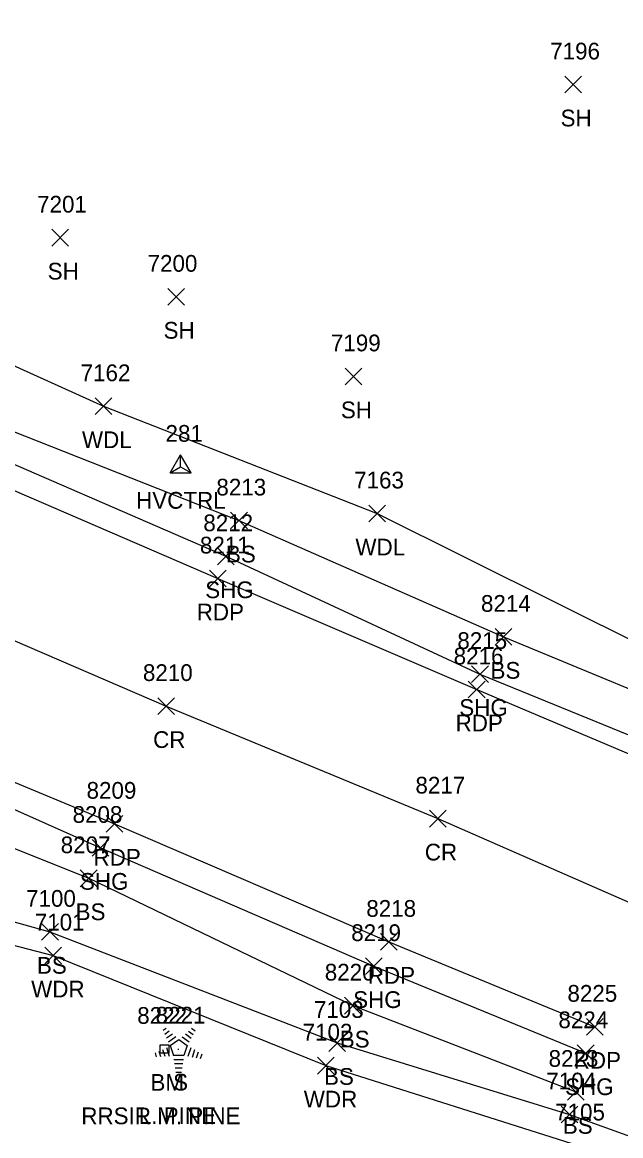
# Model space of a CAD drawing. Extents: x 1588028 to 1589597, y 137576 to 138176.
# Drawn here: x 1589378.5 to 1589450, y 137659.5 to 137792.6 of the extents above; entities that cross this region are included whole.
import ezdxf

# ---------------------------------------------------------------- set-up
doc = ezdxf.new("R2010")
doc.units = 0
for name, color, linetype in [('C_A', 7, 'Continuous'), ('C_C', 7, 'Continuous'), ('C_I', 7, 'Continuous'), ('CPBM', 7, 'Continuous'), ('CPSM', 7, 'Continuous'), ('L_A', 7, 'Continuous'), ('L_C', 7, 'Continuous'), ('L_I', 7, 'Continuous'), ('L_TIC', 7, 'Continuous'), ('LAWA', 7, 'Continuous'), ('LELB', 7, 'Continuous'), ('LTC', 7, 'Continuous'), ('P_A', 7, 'Continuous'), ('P_I', 7, 'Continuous'), ('P_TIC', 7, 'Continuous'), ('PET', 7, 'Continuous'), ('PRC', 7, 'Continuous'), ('PSU', 7, 'Continuous')]:
    doc.layers.add(name, color=color, linetype=linetype)

msp = doc.modelspace()

# ---------------------------------------------------------------- linework, layer by layer
at = {"layer": 'CPBM'}
for p, q in [((1589395.01, 137669.4), (1589395.01, 137670.4)), ((1589395.01, 137670.4), (1589396.01, 137670.4)), ((1589396.01, 137669.4), (1589395.01, 137669.4)), ((1589395.51, 137669.9), (1589395.51, 137669.9)), ((1589395.51, 137669.9), (1589395.51, 137669.9)), ((1589396.01, 137670.4), (1589396.01, 137669.4))]:
    msp.add_line(p, q, dxfattribs=at)
at = {"layer": 'CPSM'}
for p, q in [((1589396.18, 137738.74), (1589397.43, 137740.9)), ((1589398.68, 137738.74), (1589397.43, 137740.9)), ((1589397.43, 137739.46), (1589397.43, 137740.9)), ((1589396.18, 137738.74), (1589397.43, 137739.46)), ((1589396.18, 137738.74), (1589398.68, 137738.74)), ((1589397.43, 137739.46), (1589397.43, 137739.46)), ((1589397.43, 137739.46), (1589398.68, 137738.74))]:
    msp.add_line(p, q, dxfattribs=at)
at = {"layer": 'L_TIC'}
for points in [[(1589443.34, 137784.15), (1589445.34, 137786.15)], [(1589445.34, 137784.15), (1589443.34, 137786.15)], [(1589382.06, 137765.85), (1589384.06, 137767.85)], [(1589384.06, 137765.85), (1589382.06, 137767.85)], [(1589395.91, 137758.78), (1589397.91, 137760.78)], [(1589397.91, 137758.78), (1589395.91, 137760.78)], [(1589417.09, 137749.27), (1589419.09, 137751.27)], [(1589419.09, 137749.27), (1589417.09, 137751.27)], [(1589387.23, 137745.7), (1589389.23, 137747.7)], [(1589389.23, 137745.7), (1589387.23, 137747.7)], [(1589419.91, 137732.88), (1589421.91, 137734.88)], [(1589421.91, 137732.88), (1589419.91, 137734.88)], [(1589403.41, 137732.04), (1589405.41, 137734.04)], [(1589405.41, 137732.04), (1589403.41, 137734.04)], [(1589435.02, 137718.14), (1589437.02, 137720.14)], [(1589437.02, 137718.14), (1589435.02, 137720.14)], [(1589385.45, 137689.29), (1589387.45, 137691.29)], [(1589387.45, 137689.29), (1589385.45, 137691.29)], [(1589380.83, 137682.89), (1589382.83, 137684.89)], [(1589382.83, 137682.89), (1589380.83, 137684.89)], [(1589381.22, 137680.05), (1589383.22, 137682.05)], [(1589383.22, 137680.05), (1589381.22, 137682.05)], [(1589417.01, 137674.07), (1589419.01, 137676.07)], [(1589419.01, 137674.07), (1589417.01, 137676.07)], [(1589415.13, 137669.61), (1589417.13, 137671.61)], [(1589417.13, 137669.61), (1589415.13, 137671.61)], [(1589413.78, 137666.9), (1589415.78, 137668.9)], [(1589415.78, 137666.9), (1589413.78, 137668.9)], [(1589443.66, 137663.76), (1589445.66, 137665.76)], [(1589445.66, 137663.76), (1589443.66, 137665.76)], [(1589442.9, 137661.06), (1589444.9, 137663.06)], [(1589444.9, 137661.06), (1589442.9, 137663.06)]]:
    msp.add_lwpolyline(points, dxfattribs=at)
at = {"layer": 'LAWA'}
for points in [[(1589191.48, 137827.66), (1589208.47, 137821.19), (1589231.01, 137810.22), (1589260.79, 137799.99), (1589288.54, 137790.36), (1589312.49, 137778.55), (1589337.68, 137767.31), (1589356.85, 137760.89), (1589388.23, 137746.7), (1589420.91, 137733.88), (1589453.12, 137717.84), (1589474.94, 137709.38)], [(1589349.24, 137689.61), (1589382.22, 137681.05), (1589414.78, 137667.9), (1589444.95, 137658.35), (1589471.13, 137649.8)]]:
    msp.add_lwpolyline(points, dxfattribs=at)
at = {"layer": 'LELB'}
for points in [[(1589357.82, 137751.59), (1589375.51, 137744.43), (1589404.41, 137733.04), (1589436.02, 137719.14), (1589462.97, 137707.98)], [(1589348.76, 137705.36), (1589386.45, 137690.29), (1589418.01, 137675.07), (1589444.66, 137664.76)], [(1589349.04, 137693.04), (1589381.83, 137683.89), (1589416.13, 137670.61), (1589443.9, 137662.06), (1589473.48, 137651.39)]]:
    msp.add_lwpolyline(points, dxfattribs=at)
at = {"layer": 'LTC'}
for p, q in [((1589395.34, 137672.14), (1589395.7, 137672.4)), ((1589395.55, 137671.68), (1589396.08, 137672.06)), ((1589398.37, 137672.03), (1589398.92, 137671.64)), ((1589398.74, 137672.38), (1589399.16, 137672.08)), ((1589395.76, 137671.21), (1589396.47, 137671.72)), ((1589395.97, 137670.75), (1589396.85, 137671.38)), ((1589396.2, 137670.29), (1589397.21, 137671.02)), ((1589397.21, 137671.02), (1589398.21, 137670.3)), ((1589397.63, 137671.34), (1589398.44, 137670.75)), ((1589398, 137671.69), (1589398.68, 137671.19)), ((1589394.38, 137669.42), (1589394.53, 137668.95)), ((1589394.83, 137669.64), (1589395.04, 137668.99)), ((1589395.29, 137669.85), (1589395.56, 137669.02)), ((1589395.74, 137670.07), (1589396.07, 137669.05)), ((1589396.2, 137670.29), (1589396.59, 137669.1)), ((1589398.21, 137670.3), (1589397.82, 137669.1)), ((1589398.64, 137670.03), (1589398.31, 137668.99)), ((1589399.09, 137669.78), (1589398.8, 137668.89)), ((1589399.53, 137669.53), (1589399.3, 137668.8)), ((1589397.82, 137669.1), (1589396.59, 137669.1)), ((1589397.78, 137668.6), (1589396.63, 137668.6)), ((1589397.69, 137668.1), (1589396.71, 137668.1)), ((1589399.98, 137669.28), (1589399.79, 137668.7)), ((1589397.61, 137667.6), (1589396.78, 137667.6)), ((1589397.53, 137667.1), (1589396.85, 137667.1))]:
    msp.add_line(p, q, dxfattribs=at)
at = {"layer": 'P_TIC'}
for points in [[(1589401.84, 137727.77), (1589403.84, 137729.77)], [(1589403.84, 137727.77), (1589401.84, 137729.77)], [(1589400.87, 137725.11), (1589402.87, 137727.11)], [(1589402.87, 137725.11), (1589400.87, 137727.11)], [(1589432.2, 137713.7), (1589434.2, 137715.7)], [(1589434.2, 137713.7), (1589432.2, 137715.7)], [(1589431.81, 137711.85), (1589433.81, 137713.85)], [(1589433.81, 137711.85), (1589431.81, 137713.85)], [(1589394.71, 137709.87), (1589396.71, 137711.87)], [(1589396.71, 137709.87), (1589394.71, 137711.87)], [(1589388.55, 137695.8), (1589390.55, 137697.8)], [(1589390.55, 137695.8), (1589388.55, 137697.8)], [(1589427.18, 137696.42), (1589429.18, 137698.42)], [(1589429.18, 137696.42), (1589427.18, 137698.42)], [(1589386.87, 137692.92), (1589388.87, 137694.92)], [(1589388.87, 137692.92), (1589386.87, 137694.92)], [(1589421.31, 137681.69), (1589423.31, 137683.69)], [(1589423.31, 137681.69), (1589421.31, 137683.69)], [(1589419.52, 137678.79), (1589421.52, 137680.79)], [(1589421.52, 137678.79), (1589419.52, 137680.79)], [(1589445.91, 137671.54), (1589447.91, 137673.54)], [(1589447.91, 137671.54), (1589445.91, 137673.54)], [(1589444.83, 137668.38), (1589446.83, 137670.38)], [(1589446.83, 137668.38), (1589444.83, 137670.38)]]:
    msp.add_lwpolyline(points, dxfattribs=at)
at = {"layer": 'PET'}
for points in [[(1588976.42, 137837.98), (1588964.71, 137855.4), (1588953.74, 137871.46), (1588980.82, 137866.91), (1589021.21, 137859.55), (1589054.58, 137852.92), (1589087.36, 137843.77), (1589127.64, 137831.45), (1589150.05, 137824.37), (1589196.14, 137808.72), (1589243.87, 137790.96), (1589276.87, 137778.08), (1589322.25, 137759.62), (1589367.82, 137740.82), (1589401.87, 137726.11), (1589432.81, 137712.85), (1589459.76, 137701.46)], [(1588976.42, 137837.98), (1589015.38, 137829.77), (1589047.77, 137821.87), (1589087.62, 137811.07), (1589117.34, 137801.67), (1589165.82, 137785.25), (1589185.23, 137778.17), (1589232.28, 137760.8), (1589265.32, 137747.81), (1589310.31, 137729.83), (1589359.63, 137709.23), (1589389.55, 137696.8), (1589422.31, 137682.69), (1589446.91, 137672.54)]]:
    msp.add_lwpolyline(points, dxfattribs=at)
at = {"layer": 'PRC'}
msp.add_lwpolyline([(1588964.71, 137855.4), (1588980.14, 137852.51), (1589018.19, 137844.35), (1589051.57, 137836.27), (1589092.27, 137825.07), (1589122.68, 137816.23), (1589170.7, 137800.29), (1589190.72, 137793.38), (1589238.44, 137775.62), (1589271.31, 137762.4), (1589315.94, 137744.35), (1589366.22, 137723.58), (1589395.71, 137710.87), (1589428.18, 137697.42), (1589453.33, 137686.42)], dxfattribs=at)
at = {"layer": 'PSU'}
for points in [[(1589152.74, 137827.96), (1589197.07, 137811.88), (1589244.81, 137793.79), (1589277.33, 137781.11), (1589323.36, 137762.65), (1589353.23, 137749.52), (1589368.68, 137743.62), (1589402.84, 137728.77), (1589433.2, 137714.7), (1589460.72, 137703.44)], [(1589136.35, 137790.83), (1589164.04, 137781.22), (1589184.55, 137774.07), (1589230.78, 137756.58), (1589263.84, 137744.47), (1589309.17, 137726.92), (1589358.43, 137707.04), (1589387.87, 137693.92), (1589420.52, 137679.79), (1589445.83, 137669.38)]]:
    msp.add_lwpolyline(points, dxfattribs=at)

# ---------------------------------------------------------------- texts
at = {"layer": 'C_A'}
for s, p in [('HVCTRL', (1589392.12, 137734.46)), ('BM', (1589393.83, 137664.9))]:
    msp.add_text(s, height=2, dxfattribs=at).set_placement(p)
at = {"layer": 'C_C'}
msp.add_text('RRSIR M. PINE', height=2, dxfattribs=at).set_placement((1589385.57, 137660.9))
at = {"layer": 'C_I'}
for s, p in [('281', (1589395.63, 137742.46)), ('8222', (1589392.25, 137672.9))]:
    msp.add_text(s, height=2, dxfattribs=at).set_placement(p)
at = {"layer": 'L_A'}
for s, p in [('SH', (1589442.83, 137780.15)), ('SH', (1589381.55, 137761.85)), ('SH', (1589395.4, 137754.78)), ('SH', (1589416.58, 137745.27)), ('WDL', (1589385.65, 137741.7)), ('WDL', (1589418.32, 137728.88)), ('BS', (1589402.85, 137728.04)), ('BS', (1589434.46, 137714.14)), ('BS', (1589384.89, 137685.29)), ('BS', (1589380.27, 137678.89)), ('WDR', (1589379.58, 137676.05)), ('BS', (1589416.45, 137670.07)), ('S', (1589396.54, 137664.93)), ('BS', (1589414.57, 137665.61)), ('WDR', (1589412.15, 137662.9)), ('BS', (1589443.1, 137659.76))]:
    msp.add_text(s, height=2, dxfattribs=at).set_placement(p)
at = {"layer": 'L_C'}
msp.add_text('L. PINE', height=2, dxfattribs=at).set_placement((1589392.44, 137660.93))
at = {"layer": 'L_I'}
for s, p in [('7196', (1589441.59, 137788.15)), ('7201', (1589380.29, 137769.85)), ('7200', (1589393.49, 137762.78)), ('7199', (1589415.39, 137753.27)), ('7162', (1589385.49, 137749.7)), ('7163', (1589418.17, 137736.88)), ('8213', (1589401.71, 137736.04)), ('8214', (1589433.32, 137722.14)), ('8207', (1589383.11, 137693.29)), ('7100', (1589378.97, 137686.89)), ('7101', (1589380.01, 137684.05)), ('8220', (1589414.66, 137678.07)), ('8221', (1589394.46, 137672.93)), ('7103', (1589413.36, 137673.61)), ('7102', (1589412.01, 137670.9)), ('8223', (1589441.4, 137667.76)), ('7104', (1589441.13, 137665.06)), ('7105', (1589442.18, 137661.35))]:
    msp.add_text(s, height=2, dxfattribs=at).set_placement(p)
at = {"layer": 'LTC'}
msp.add_text('.', height=1.04, rotation=270, dxfattribs=at).set_placement((1589397.09, 137670.04))
at = {"layer": 'P_A'}
for s, p in [('SHG', (1589400.38, 137723.77)), ('RDP', (1589399.36, 137721.11)), ('SHG', (1589430.73, 137709.7)), ('RDP', (1589430.29, 137707.85)), ('CR', (1589394.15, 137705.87)), ('RDP', (1589387.03, 137691.8)), ('CR', (1589426.61, 137692.42)), ('SHG', (1589385.41, 137688.92)), ('RDP', (1589419.8, 137677.69)), ('SHG', (1589418.05, 137674.79)), ('RDP', (1589444.4, 137667.54)), ('SHG', (1589443.37, 137664.38))]:
    msp.add_text(s, height=2, dxfattribs=at).set_placement(p)
at = {"layer": 'P_I'}
for s, p in [('8212', (1589400.15, 137731.77)), ('8211', (1589399.74, 137729.11)), ('8215', (1589430.5, 137717.7)), ('8216', (1589430.06, 137715.85)), ('8210', (1589392.93, 137713.87)), ('8209', (1589386.2, 137699.8)), ('8217', (1589425.49, 137700.42)), ('8208', (1589384.53, 137696.92)), ('8218', (1589419.62, 137685.69)), ('8219', (1589417.82, 137682.79)), ('8225', (1589443.65, 137675.54)), ('8224', (1589442.57, 137672.38))]:
    msp.add_text(s, height=2, dxfattribs=at).set_placement(p)

doc.saveas('drawing.dxf')
